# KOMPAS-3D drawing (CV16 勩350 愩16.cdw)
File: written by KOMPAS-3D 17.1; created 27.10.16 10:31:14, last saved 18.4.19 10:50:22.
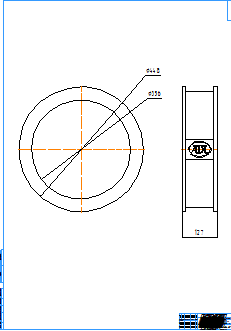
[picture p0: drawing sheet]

Sheet 1: A0, portrait

Title block, sheet 1: name: CV16 Ду350 Ру16; material: Внимание! Данный продукт является объектом авторского права ООО «Торговый Дом АДЛ». / Запрещается изменение, копирование, распространение / (в том числе путем копирования на другие сайты и ресурсы в Интернете) / или любое иное использование информации и объектов без предварительного / согласия правообладателя (ООО «Торговый Дом АДЛ»).; mass: 55; sheets: 1; organisation: ООО "Торговый дом АДЛ"; sheet format: A0; stored path: \\adlc.lan\data\АДЛ_ПКД\3D-модели\ADL production\Клапаны обратные ГРАНЛОК\CV16\KOMPAS 2D\CV16 Ду350 Ру16.cdw

Views: Вид 1, Проекционный вид 2
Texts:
  Klimkovich
  ADL
Dimensions and other numbers on the sheet: 448; 356; 127; 1:1; 1; 55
